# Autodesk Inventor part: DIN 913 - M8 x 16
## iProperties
Created: 2006-02
Part Number: DIN 913 - M8 x 16
Material: Steel, Mild
Description: Hexagon Socket Set Screw
Document SubType Name: Modeling
Standard: DIN 913
Designer: Andy Moles
Standards Organization: DIN
Language: en-US
Size Designation: M8 x 16
Categories: <MemberInstance><Categories><Category DisplayName="Fasteners" InternalName="e4da775c-781d-43d5-af7c-5136215cf5a6" Mnemonic="FSTN"><Category DisplayName="Bolts"
Density: 1 g/cm^3
Author: Andy Moles
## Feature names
1. Body [Revolution]
2. Slot [Extrusion]
3. Chamfer1
4. Chamfer2
